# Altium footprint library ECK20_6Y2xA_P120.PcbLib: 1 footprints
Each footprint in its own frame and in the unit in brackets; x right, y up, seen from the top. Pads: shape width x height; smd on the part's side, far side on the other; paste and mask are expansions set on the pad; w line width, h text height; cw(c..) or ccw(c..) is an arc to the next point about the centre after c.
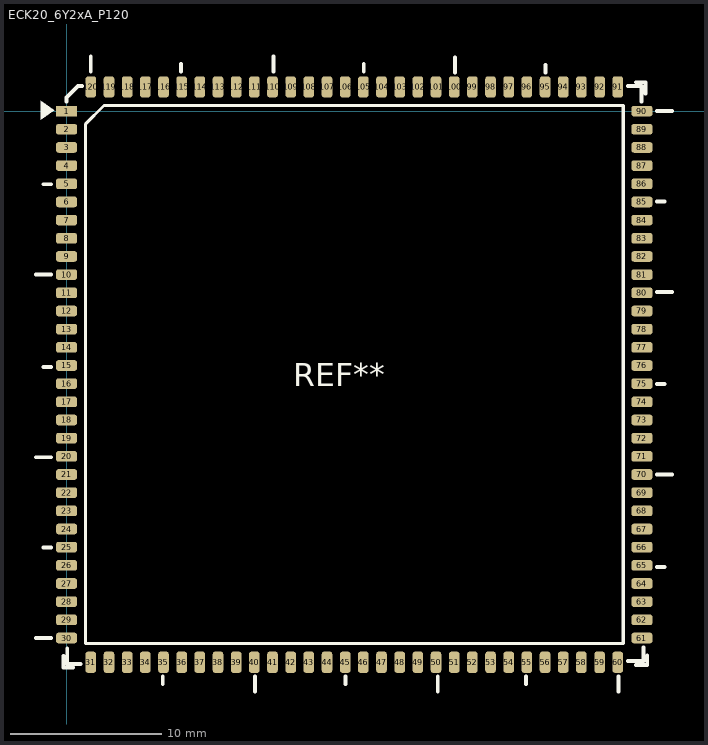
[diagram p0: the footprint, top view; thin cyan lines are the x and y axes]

## ECK20_6Y2xA_P120 [mm]
pads (120):
  rect 1.4x0.7 smd: 1(0,0)
  rrect50% 1.4x0.7 smd: 2(0,-1.2) 3(0,-2.4) 4(0,-3.6) 5(0,-4.8) 6(0,-6) 7(0,-7.2) 8(0,-8.4) 9(0,-9.6) 10(0,-10.8) 11(0,-12) 12(0,-13.2) 13(0,-14.4) 14(0,-15.6) 15(0,-16.8) 16(0,-18) 17(0,-19.2) 18(0,-20.4) 19(0,-21.6) 20(0,-22.8) 21(0,-24) 22(0,-25.2) 23(0,-26.4) 24(0,-27.6) 25(0,-28.8) 26(0,-30) 27(0,-31.2) 28(0,-32.4) 29(0,-33.6) 30(0,-34.8) 61(38,-34.8) 62(38,-33.6) 63(38,-32.4) 64(38,-31.2) 65(38,-30) 66(38,-28.8) 67(38,-27.6) 68(38,-26.4) 69(38,-25.2) 70(38,-24) 71(38,-22.8) 72(38,-21.6) 73(38,-20.4) 74(38,-19.2) 75(38,-18) 76(38,-16.8) 77(38,-15.6) 78(38,-14.4) 79(38,-13.2) 80(38,-12) 81(38,-10.8) 82(38,-9.6) 83(38,-8.4) 84(38,-7.2) 85(38,-6) 86(38,-4.8) 87(38,-3.6) 88(38,-2.4) 89(38,-1.2) 90(38,0)
  rrect50% 0.7x1.4 smd: 31(1.6,-36.4) 32(2.8,-36.4) 33(4,-36.4) 34(5.2,-36.4) 35(6.4,-36.4) 36(7.6,-36.4) 37(8.8,-36.4) 38(10,-36.4) 39(11.2,-36.4) 40(12.4,-36.4) 41(13.6,-36.4) 42(14.8,-36.4) 43(16,-36.4) 44(17.2,-36.4) 45(18.4,-36.4) 46(19.6,-36.4) 47(20.8,-36.4) 48(22,-36.4) 49(23.2,-36.4) 50(24.4,-36.4) 51(25.6,-36.4) 52(26.8,-36.4) 53(28,-36.4) 54(29.2,-36.4) 55(30.4,-36.4) 56(31.6,-36.4) 57(32.8,-36.4) 58(34,-36.4) 59(35.2,-36.4) 60(36.4,-36.4) 91(36.4,1.6) 92(35.2,1.6) 93(34,1.6) 94(32.8,1.6) 95(31.6,1.6) 96(30.4,1.6) 97(29.2,1.6) 98(28,1.6) 99(26.8,1.6) 100(25.6,1.6) 101(24.4,1.6) 102(23.2,1.6) 103(22,1.6) 104(20.8,1.6) 105(19.6,1.6) 106(18.4,1.6) 107(17.2,1.6) 108(16,1.6) 109(14.8,1.6) 110(13.6,1.6) 111(12.4,1.6) 112(11.2,1.6) 113(10,1.6) 114(8.8,1.6) 115(7.6,1.6) 116(6.4,1.6) 117(5.2,1.6) 118(4,1.6) 119(2.8,1.6) 120(1.6,1.6)
Top Overlay:
  region: -1.714,-0.572 -0.826,0.064 -1.714,0.699
  lines w0.2: 1.235,-35.165 36.765,-35.165 36.765,0.365 2.47,0.365 1.235,-0.87 1.235,-35.165
  lines w0.254: -2.032,-34.798 -1.032,-34.798 ; -2.032,-22.86 -1.032,-22.86 ; -2.032,-10.795 -1.032,-10.795 ; -1.516,-28.829 -1.016,-28.829 ; -1.516,-16.891 -1.016,-16.891 ; -1.516,-4.826 -1.016,-4.826 ; -0.203,-35.992 -0.203,-36.754 0.432,-36.754 ; 0,0.635 0,0.889 0.762,1.651 1.016,1.651 ; 0.048,-35.498 0.048,-36.514 0.937,-36.514 ; 1.594,2.613 1.594,3.613 ; 6.35,-37.846 6.35,-37.346 ; 7.563,2.605 7.563,3.105 ; 12.446,-38.338 12.446,-37.338 ; 13.659,2.613 13.659,3.613 ; 18.415,-37.846 18.415,-37.346 ; 19.628,2.605 19.628,3.105 ; 24.511,-38.338 24.511,-37.338 ; 25.654,2.556 25.654,3.556 ; 30.353,-37.846 30.353,-37.346 ; 31.623,2.548 31.623,3.048 ; 36.449,-38.338 36.449,-37.338 ; 37.084,-36.322 38.1,-36.322 38.1,-35.433 ; 37.084,1.651 37.973,1.651 37.973,0.635 ; 37.592,-36.576 38.354,-36.576 38.354,-35.941 ; 37.592,1.905 38.227,1.905 38.227,1.143 ; 38.989,-24.003 39.989,-24.003 ; 38.989,-11.938 39.989,-11.938 ; 38.997,-30.099 39.497,-30.099 ; 38.997,-18.034 39.497,-18.034 ; 38.997,-5.969 39.497,-5.969 ; 38.997,0 39.247,0 39.747,0 39.997,0
  text "REF**" at 14.986,-18.161 h1.52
